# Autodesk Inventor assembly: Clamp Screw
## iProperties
Shininess: 50.0
Length Units: 11272
Angle Units: 11279
Time Units: 11290
Mass Units: 11286
Length Display Precision: 4
Angle Display Precision: 2
Company: Autodesk
Manager: Lebovitz
Created: 2000-11
Part Number: Clamp Screw
Document SubType Name: Assembly
Designer: The PD Team
Project: Inventor Samples
Checked By: The PD Team
Density: 0.0
Volumn: 0.0
Area: 0.0
PropertySet Name: Model Information
Control State: 0
Master: False
Checked Out: False
Author: The PD Team
Revision Number: A
